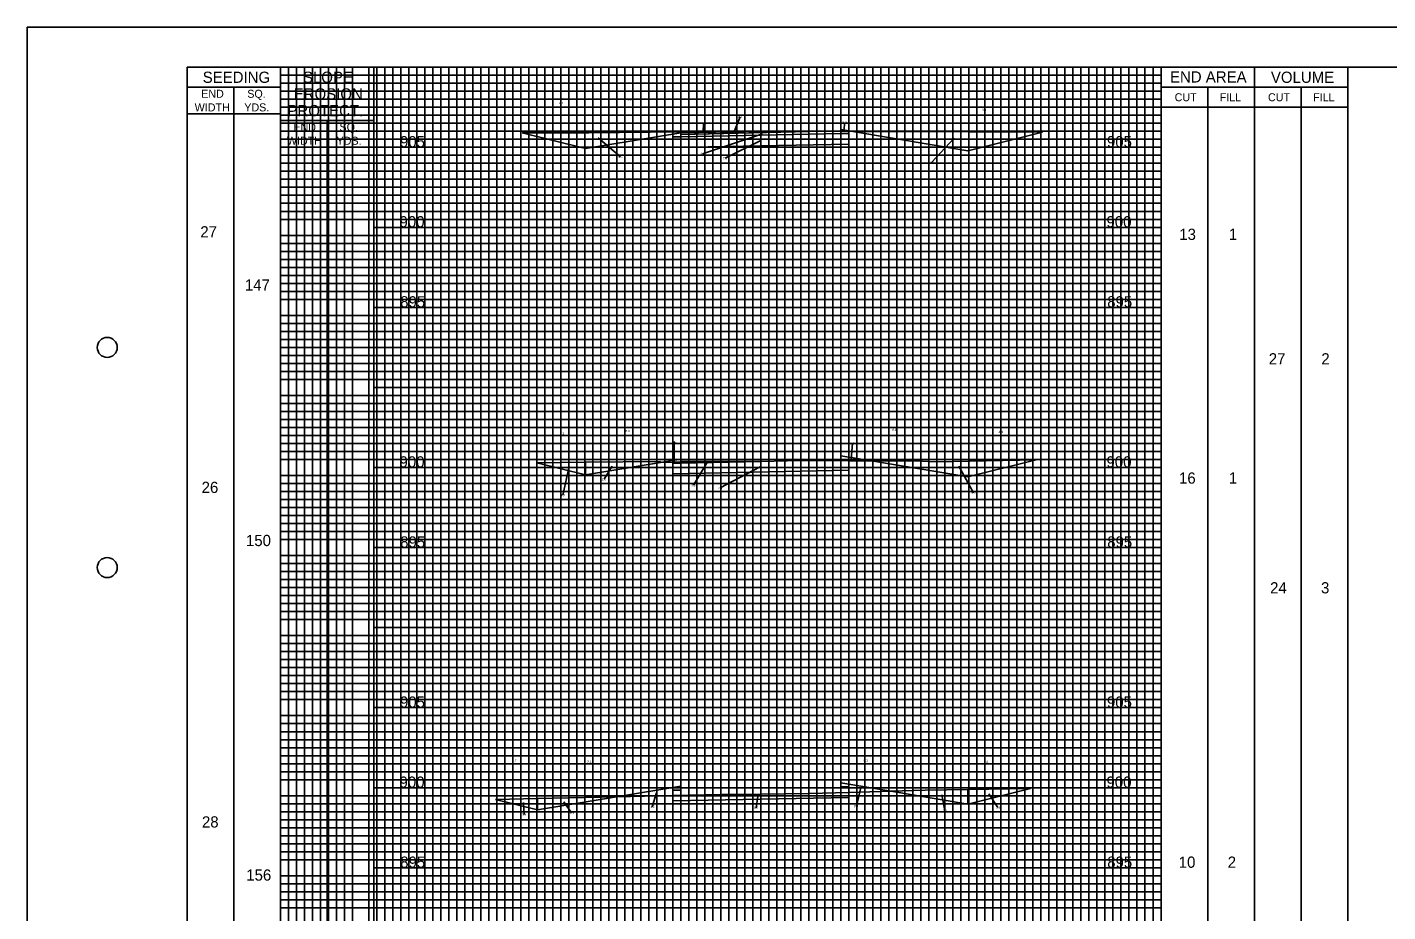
# Model space of a CAD drawing. Extents: x -73 to 160, y -2 to 1877.
# Drawn here: x -10 to 75, y 167.2 to 222.5 of the extents above; entities that cross this region are included whole.
import ezdxf

# ---------------------------------------------------------------- set-up
doc = ezdxf.new("R2010")
doc.units = 0
for name, color, linetype in [('DR_P_Flood_Boundary', 7, 'Continuous'), ('GK_Cells', 7, 'Continuous'), ('RD_X_Fence', 7, 'Continuous'), ('TX_X_5', 7, 'Continuous'), ('UT_P_Water_Cells', 7, 'Continuous'), ('XS_P_Pavt_Surface', 7, 'Continuous'), ('XS_X_Ground_Line', 7, 'Continuous')]:
    doc.layers.add(name, color=color, linetype=linetype)

msp = doc.modelspace()

# ---------------------------------------------------------------- linework, layer by layer
at = {"layer": 'DR_P_Flood_Boundary'}
for p, q in [((15.832, 115), (15.832, 220)), ((20.832, 115), (20.832, 220)), ((25.832, 115), (25.832, 220)), ((30.832, 115), (30.832, 220)), ((35.832, 115), (35.832, 220)), ((40.832, 115), (40.832, 220)), ((45.832, 115), (45.832, 220)), ((50.832, 115), (50.832, 220)), ((55.832, 115), (55.832, 220)), ((5.832, 215), (60.832, 215)), ((11.665, 210), (60.832, 210)), ((11.665, 205), (60.832, 205)), ((11.665, 200), (60.832, 200)), ((11.665, 195), (60.832, 195)), ((11.665, 190), (60.832, 190)), ((11.665, 185), (60.832, 185)), ((11.665, 180), (60.832, 180)), ((11.665, 175), (60.832, 175)), ((11.665, 170), (60.832, 170))]:
    msp.add_line(p, q, dxfattribs=at)
at = {"layer": 'GK_Cells'}
msp.add_lwpolyline([(0, 220), (157.5, 220), (157.5, 115), (0, 115)], close=True, dxfattribs=at)
for centre in [(-5, 202.5), (-5, 188.75)]:
    msp.add_circle(centre, 0.625, dxfattribs=at)
at = {"layer": 'RD_X_Fence'}
for p, q in [((34.135, 215.924), (34.547, 216.895)), ((20.929, 215.905), (24.878, 214.918)), ((24.878, 214.918), (30.832, 215.91)), ((30.832, 215.967), (25.09, 215.91)), ((34.134, 215.994), (30.832, 215.963)), ((30.832, 215.91), (34.134, 215.976)), ((30.832, 215.91), (30.832, 215.806)), ((32.212, 215.957), (32.267, 216.487)), ((34.134, 215.976), (34.134, 215.976)), ((38.879, 215.983), (36.067, 216.015)), ((40.832, 216.11), (40.832, 216.026)), ((41.376, 216.019), (40.832, 216.11)), ((40.832, 215.86), (40.832, 216.026)), ((41.014, 216.052), (41.088, 216.554)), ((41.586, 215.984), (48.773, 214.787)), ((48.773, 214.787), (53.432, 215.951)), ((25.668, 215.588), (27.062, 214.401)), ((30.832, 215.66), (30.332, 215.65)), ((30.332, 215.65), (30.332, 214.983)), ((30.332, 214.983), (41.332, 215.203)), ((30.832, 215.66), (40.832, 215.86)), ((30.832, 215.806), (30.832, 215.66)), ((35.938, 215.84), (32.185, 214.59)), ((35.832, 215.427), (33.595, 214.316)), ((41.332, 215.203), (41.332, 215.87)), ((47.918, 215.577), (46.501, 214.041)), ((30.411, 195.394), (30.418, 196.617)), ((41.485, 195.521), (41.552, 196.492)), ((30.832, 195.53), (29.569, 195.319)), ((30.832, 195.381), (30.832, 195.53)), ((40.832, 195.73), (40.832, 195.626)), ((42.749, 195.411), (40.832, 195.73)), ((40.832, 195.626), (40.832, 195.626)), ((40.832, 195.626), (40.832, 195.433)), ((24.878, 195.331), (21.836, 195.298)), ((21.836, 195.298), (24.878, 194.538)), ((23.864, 195.055), (23.465, 193.264)), ((29.559, 195.381), (24.878, 195.331)), ((24.878, 194.538), (24.878, 195.331)), ((24.878, 195.331), (24.878, 194.538)), ((24.878, 194.538), (29.569, 195.319)), ((26.554, 195.083), (26.037, 194.266)), ((30.332, 195.27), (30.332, 194.603)), ((30.332, 194.603), (41.332, 194.823)), ((35.834, 195.38), (30.832, 195.381)), ((30.832, 195.381), (30.832, 195.28)), ((30.832, 195.332), (30.832, 195.381)), ((30.832, 195.28), (35.834, 195.38)), ((32.5, 195.347), (31.624, 193.899)), ((35.786, 195.043), (33.289, 193.722)), ((38.94, 195.442), (37.476, 195.413)), ((40.832, 195.433), (41.332, 195.43)), ((41.332, 194.823), (41.332, 195.43)), ((41.332, 195.43), (41.332, 195.411)), ((41.332, 195.411), (42.749, 195.411)), ((42.749, 195.411), (48.773, 194.407)), ((48.192, 195.075), (49.12, 193.427)), ((48.773, 194.407), (53.031, 195.471)), ((30.832, 175.103), (26.82, 174.435)), ((43.944, 174.785), (40.832, 175.303)), ((21.878, 174.324), (19.259, 174.266)), ((19.259, 174.266), (21.878, 173.611)), ((21.878, 173.611), (26.82, 174.435)), ((26.82, 174.435), (21.878, 174.324)), ((21.878, 174.324), (21.878, 173.611)), ((21.878, 173.611), (21.878, 174.324)), ((26.82, 174.435), (30.332, 174.513)), ((29.315, 174.688), (29.051, 173.807)), ((30.332, 174.843), (30.832, 174.853)), ((30.332, 174.513), (30.332, 174.843)), ((30.332, 174.513), (30.332, 174.177)), ((30.332, 174.177), (41.332, 174.397)), ((35.644, 174.442), (35.531, 173.749)), ((40.832, 175.053), (41.332, 175.063)), ((41.332, 175.063), (41.332, 174.705)), ((41.332, 174.705), (43.944, 174.785)), ((41.332, 174.397), (41.332, 174.705)), ((42.053, 174.937), (41.799, 173.848)), ((43.944, 174.785), (48.773, 173.98)), ((47.146, 174.558), (47.334, 173.564)), ((48.773, 173.98), (52.675, 174.955)), ((52.675, 174.955), (48.773, 174.894)), ((48.773, 174.894), (48.773, 173.98)), ((48.773, 173.98), (48.773, 174.894)), ((50.074, 174.61), (50.648, 173.769)), ((21.005, 174.067), (21.049, 173.335)), ((23.525, 174.123), (24.014, 173.429))]:
    msp.add_line(p, q, dxfattribs=at)
for points in [[(25.09, 215.91), (22.415, 215.896), (20.929, 215.905)], [(40.832, 216.026), (38.879, 215.983), (30.832, 215.806)], [(36.067, 216.015), (35.833, 216.01), (30.832, 215.91)], [(30.832, 215.806), (35.937, 215.918), (38.879, 215.983)], [(30.832, 215.91), (30.832, 215.967)], [(30.832, 215.963), (30.832, 215.91)], [(34.134, 215.976), (34.134, 215.994)], [(40.832, 216.026), (40.833, 216.026), (41.376, 216.019)], [(53.432, 215.951), (44.275, 215.986), (41.586, 215.984)], [(41.332, 215.87), (40.832, 215.86), (30.832, 215.66)], [(40.832, 195.626), (40.832, 195.626)], [(29.569, 195.319), (29.559, 195.381)], [(29.569, 195.319), (30.332, 195.327), (30.832, 195.332), (30.832, 195.332)], [(37.476, 195.413), (35.834, 195.38), (30.832, 195.28), (30.332, 195.27)], [(41.332, 195.43), (41.332, 195.43), (40.832, 195.433), (38.94, 195.442)], [(53.031, 195.471), (46.816, 195.359), (45.485, 195.409), (42.749, 195.411)], [(30.832, 174.853), (30.832, 174.999), (30.832, 175.103)], [(40.832, 175.303), (40.832, 175.199), (40.832, 175.053)], [(41.332, 174.705), (38.848, 174.628), (35.833, 174.603), (33.421, 174.582), (30.332, 174.513)], [(48.773, 174.894), (46.098, 174.851), (43.944, 174.785)]]:
    msp.add_lwpolyline(points, dxfattribs=at)
at = {"layer": 'TX_X_5'}
msp.add_lwpolyline([(-10, 112.5), (160, 112.5), (160, 222.5), (-10, 222.5)], close=True, dxfattribs=at)
at = {"layer": 'UT_P_Water_Cells'}
for p, q in [((5.832, 219.5), (60.832, 219.5)), ((6.332, 115), (6.332, 220)), ((6.832, 115), (6.832, 220)), ((7.332, 115), (7.332, 220)), ((7.832, 115), (7.832, 220)), ((8.332, 115), (8.332, 220)), ((8.832, 115), (8.832, 220)), ((9.332, 115), (9.332, 220)), ((9.832, 115), (9.832, 220)), ((10.332, 115), (10.332, 220)), ((11.332, 115), (11.332, 220)), ((11.832, 115), (11.832, 220)), ((12.332, 115), (12.332, 220)), ((12.832, 115), (12.832, 220)), ((13.332, 115), (13.332, 220)), ((13.832, 115), (13.832, 220)), ((14.332, 115), (14.332, 220)), ((14.832, 115), (14.832, 220)), ((15.332, 115), (15.332, 220)), ((16.332, 115), (16.332, 220)), ((16.832, 115), (16.832, 220)), ((17.332, 115), (17.332, 220)), ((17.832, 115), (17.832, 220)), ((18.332, 115), (18.332, 220)), ((18.832, 115), (18.832, 220)), ((19.332, 115), (19.332, 220)), ((19.832, 115), (19.832, 220)), ((20.332, 115), (20.332, 220)), ((21.332, 115), (21.332, 220)), ((21.832, 115), (21.832, 220)), ((22.332, 115), (22.332, 220)), ((22.832, 115), (22.832, 220)), ((23.332, 115), (23.332, 220)), ((23.832, 115), (23.832, 220)), ((24.332, 115), (24.332, 220)), ((24.832, 115), (24.832, 220)), ((25.332, 115), (25.332, 220)), ((26.332, 115), (26.332, 220)), ((26.832, 115), (26.832, 220)), ((27.332, 115), (27.332, 220)), ((27.832, 115), (27.832, 220)), ((28.332, 115), (28.332, 220)), ((28.832, 115), (28.832, 220)), ((29.332, 115), (29.332, 220)), ((29.832, 115), (29.832, 220)), ((30.332, 115), (30.332, 220)), ((31.332, 115), (31.332, 220)), ((31.832, 115), (31.832, 220)), ((32.332, 115), (32.332, 220)), ((32.832, 115), (32.832, 220)), ((33.332, 115), (33.332, 220)), ((33.832, 115), (33.832, 220)), ((34.332, 115), (34.332, 220)), ((34.832, 115), (34.832, 220)), ((35.332, 115), (35.332, 220)), ((36.332, 115), (36.332, 220)), ((36.832, 115), (36.832, 220)), ((37.332, 115), (37.332, 220)), ((37.832, 115), (37.832, 220)), ((38.332, 115), (38.332, 220)), ((38.832, 115), (38.832, 220)), ((39.332, 115), (39.332, 220)), ((39.832, 115), (39.832, 220)), ((40.332, 115), (40.332, 220)), ((41.332, 115), (41.332, 220)), ((41.832, 115), (41.832, 220)), ((42.332, 115), (42.332, 220)), ((42.832, 115), (42.832, 220)), ((43.332, 115), (43.332, 220)), ((43.832, 115), (43.832, 220)), ((44.332, 115), (44.332, 220)), ((44.832, 115), (44.832, 220)), ((45.332, 115), (45.332, 220)), ((46.332, 115), (46.332, 220)), ((46.832, 115), (46.832, 220)), ((47.332, 115), (47.332, 220)), ((47.832, 115), (47.832, 220)), ((48.332, 115), (48.332, 220)), ((48.832, 115), (48.832, 220)), ((49.332, 115), (49.332, 220)), ((49.832, 115), (49.832, 220)), ((50.332, 115), (50.332, 220)), ((51.332, 115), (51.332, 220)), ((51.832, 115), (51.832, 220)), ((52.332, 115), (52.332, 220)), ((52.832, 115), (52.832, 220)), ((53.332, 115), (53.332, 220)), ((53.832, 115), (53.832, 220)), ((54.332, 115), (54.332, 220)), ((54.832, 115), (54.832, 220)), ((55.332, 115), (55.332, 220)), ((56.332, 115), (56.332, 220)), ((56.832, 115), (56.832, 220)), ((57.332, 115), (57.332, 220)), ((57.832, 115), (57.832, 220)), ((58.332, 115), (58.332, 220)), ((58.832, 115), (58.832, 220)), ((59.332, 115), (59.332, 220)), ((59.832, 115), (59.832, 220)), ((60.332, 115), (60.332, 220)), ((5.832, 219), (60.832, 219)), ((5.832, 218.5), (60.832, 218.5)), ((5.832, 218), (60.832, 218)), ((5.832, 217.5), (60.832, 217.5)), ((5.832, 217), (60.832, 217)), ((5.832, 216.5), (60.832, 216.5)), ((5.832, 216), (60.832, 216)), ((5.832, 215.5), (60.832, 215.5)), ((5.832, 214.5), (60.832, 214.5)), ((5.832, 214), (60.832, 214)), ((5.832, 213.5), (60.832, 213.5)), ((5.832, 213), (60.832, 213)), ((5.832, 212.5), (60.832, 212.5)), ((5.832, 212), (60.832, 212)), ((5.832, 211.5), (60.832, 211.5)), ((5.832, 211), (60.832, 211)), ((5.832, 210.5), (60.832, 210.5)), ((5.832, 209.5), (60.832, 209.5)), ((5.832, 209), (60.832, 209)), ((5.832, 208.5), (60.832, 208.5)), ((5.832, 208), (60.832, 208)), ((5.832, 207.5), (60.832, 207.5)), ((5.832, 207), (60.832, 207)), ((5.832, 206.5), (60.832, 206.5)), ((5.832, 206), (60.832, 206)), ((5.832, 205.5), (60.832, 205.5)), ((5.832, 204.5), (60.832, 204.5)), ((5.832, 204), (60.832, 204)), ((5.832, 203.5), (60.832, 203.5)), ((5.832, 203), (60.832, 203)), ((5.832, 202.5), (60.832, 202.5)), ((5.832, 202), (60.832, 202)), ((5.832, 201.5), (60.832, 201.5)), ((5.832, 201), (60.832, 201)), ((5.832, 200.5), (60.832, 200.5)), ((5.832, 199.5), (60.832, 199.5)), ((5.832, 199), (60.832, 199)), ((5.832, 198.5), (60.832, 198.5)), ((5.832, 198), (60.832, 198)), ((5.832, 197.5), (60.832, 197.5)), ((5.832, 197), (60.832, 197)), ((5.832, 196.5), (60.832, 196.5)), ((5.832, 196), (60.832, 196)), ((5.832, 195.5), (60.832, 195.5)), ((5.832, 194.5), (60.832, 194.5)), ((5.832, 194), (60.832, 194)), ((5.832, 193.5), (60.832, 193.5)), ((5.832, 193), (60.832, 193)), ((5.832, 192.5), (60.832, 192.5)), ((5.832, 192), (60.832, 192)), ((5.832, 191.5), (60.832, 191.5)), ((5.832, 191), (60.832, 191)), ((5.832, 190.5), (60.832, 190.5)), ((5.832, 189.5), (60.832, 189.5)), ((5.832, 189), (60.832, 189)), ((5.832, 188.5), (60.832, 188.5)), ((5.832, 188), (60.832, 188)), ((5.832, 187.5), (60.832, 187.5)), ((5.832, 187), (60.832, 187)), ((5.832, 186.5), (60.832, 186.5)), ((5.832, 186), (60.832, 186)), ((5.832, 185.5), (60.832, 185.5)), ((5.832, 184.5), (60.832, 184.5)), ((5.832, 184), (60.832, 184)), ((5.832, 183.5), (60.832, 183.5)), ((5.832, 183), (60.832, 183)), ((5.832, 182.5), (60.832, 182.5)), ((5.832, 182), (60.832, 182)), ((5.832, 181.5), (60.832, 181.5)), ((5.832, 181), (60.832, 181)), ((5.832, 180.5), (60.832, 180.5)), ((5.832, 179.5), (60.832, 179.5)), ((5.832, 179), (60.832, 179)), ((5.832, 178.5), (60.832, 178.5)), ((5.832, 178), (60.832, 178)), ((5.832, 177.5), (60.832, 177.5)), ((5.832, 177), (60.832, 177)), ((5.832, 176.5), (60.832, 176.5)), ((5.832, 176), (60.832, 176)), ((5.832, 175.5), (60.832, 175.5)), ((5.832, 174.5), (60.832, 174.5)), ((5.832, 174), (60.832, 174)), ((5.832, 173.5), (60.832, 173.5)), ((5.832, 173), (60.832, 173)), ((5.832, 172.5), (60.832, 172.5)), ((5.832, 172), (60.832, 172)), ((5.832, 171.5), (60.832, 171.5)), ((5.832, 171), (60.832, 171)), ((5.832, 170.5), (60.832, 170.5)), ((5.832, 169.5), (60.832, 169.5)), ((5.832, 169), (60.832, 169)), ((5.832, 168.5), (60.832, 168.5)), ((5.832, 168), (60.832, 168)), ((5.832, 167.5), (60.832, 167.5))]:
    msp.add_line(p, q, dxfattribs=at)
at = {"layer": 'XS_X_Ground_Line'}
for p, q in [((5.832, 115), (5.832, 220)), ((5.832, 115), (5.832, 220)), ((11.665, 115), (11.665, 220)), ((60.832, 115), (60.832, 220)), ((66.667, 115), (66.667, 220)), ((72.5, 115), (72.5, 220)), ((5.832, 218.75), (0, 218.75)), ((2.916, 115), (2.916, 218.75)), ((60.832, 218.75), (72.5, 218.75)), ((63.75, 115), (63.75, 218.75)), ((69.583, 115), (69.583, 218.75)), ((5.832, 217.083), (0, 217.083)), ((60.832, 217.5), (72.5, 217.5)), ((11.665, 216.667), (5.832, 216.667)), ((8.749, 115), (8.749, 216.667)), ((11.665, 215), (5.832, 215))]:
    msp.add_line(p, q, dxfattribs=at)

# ---------------------------------------------------------------- texts
at = {"layer": 'RD_X_Fence'}
for s, p in [('4.1', (23.219, 217.698)), ('6.0', (27.486, 217.915)), ('0.7', (34.394, 216.825)), ('8.1', (43.612, 217.419)), ('4.8', (49.641, 217.272)), ('0.1', (32.14, 216.417)), ('0.0', (40.929, 216.484)), ('5.1', (26.942, 214.331)), ('1.6', (32.062, 214.52)), ('7.3', (33.45, 214.246)), ('7.0', (46.35, 213.971)), ('3.1', (23.28, 197.06)), ('6.0', (27.38, 197.209)), ('8.1', (44.041, 197.284)), ('4.4', (50.688, 197.153)), ('0.1', (30.292, 196.547)), ('0.3', (41.399, 196.422)), ('2.0', (25.886, 194.196)), ('0.3', (31.472, 193.829)), ('1.2', (23.347, 193.194)), ('7.3', (33.144, 193.652)), ('5.0', (48.968, 193.357)), ('2.7', (20.295, 176.633)), ('9.1', (24.975, 176.571)), ('8.1', (42.249, 176.633)), ('4.0', (49.764, 176.54)), ('0.9', (20.895, 173.265)), ('1.8', (23.895, 173.359)), ('1.0', (28.927, 173.737)), ('3.5', (35.384, 173.679)), ('0.8', (41.646, 173.778)), ('2.2', (47.189, 173.494)), ('1.8', (50.529, 173.699))]:
    msp.add_text(s, height=0.14, dxfattribs=at).set_placement(p)
at = {"layer": 'XS_P_Pavt_Surface'}
for s, p in [('905', (13.287, 215)), ('905', (57.454, 215)), ('27', (0.814, 209.37)), ('900', (13.259, 210)), ('900', (57.427, 210)), ('13', (61.972, 209.214)), ('1', (65.064, 209.214)), ('147', (3.6, 206.053)), ('895', (13.303, 205)), ('895', (57.471, 205)), ('27', (67.564, 201.439)), ('2', (70.849, 201.439)), ('900', (13.259, 195)), ('900', (57.427, 195)), ('16', (61.958, 193.991)), ('1', (65.064, 193.991)), ('26', (0.896, 193.409)), ('150', (3.666, 190.092)), ('895', (13.303, 190)), ('895', (57.471, 190)), ('24', (67.649, 187.137)), ('3', (70.829, 187.137)), ('905', (13.287, 180)), ('905', (57.454, 180)), ('900', (13.259, 175)), ('900', (57.427, 175)), ('28', (0.915, 172.514)), ('895', (13.303, 170)), ('895', (57.471, 170)), ('10', (61.939, 170)), ('2', (65.001, 170)), ('156', (3.685, 169.197))]:
    msp.add_text(s, height=0.7, dxfattribs=at).set_placement(p)
at = {"layer": 'XS_X_Ground_Line'}
for s, height, p in [('SEEDING', 0.7, (0.964, 219.025)), ('SLOPE', 0.7, (7.228, 219.025)), ('END AREA', 0.7, (61.394, 219.047)), ('VOLUME', 0.7, (67.698, 219.025)), ('END', 0.5, (0.87, 218.092)), ('SQ.', 0.5, (3.748, 218.092)), ('EROSION', 0.7, (6.649, 217.983)), ('WIDTH', 0.5, (0.462, 217.242)), ('YDS.', 0.5, (3.563, 217.242)), ('PROTECT.', 0.7, (6.26, 216.942)), ('CUT', 0.5, (61.683, 217.875)), ('FILL', 0.5, (64.502, 217.875)), ('CUT', 0.5, (67.517, 217.875)), ('FILL', 0.5, (70.335, 217.875)), ('END', 0.5, (6.631, 216.008)), ('SQ.', 0.5, (9.51, 216.008)), ('WIDTH', 0.5, (6.224, 215.158)), ('YDS.', 0.5, (9.325, 215.158))]:
    msp.add_text(s, height=height, dxfattribs=at).set_placement(p)

doc.saveas('drawing.dxf')
